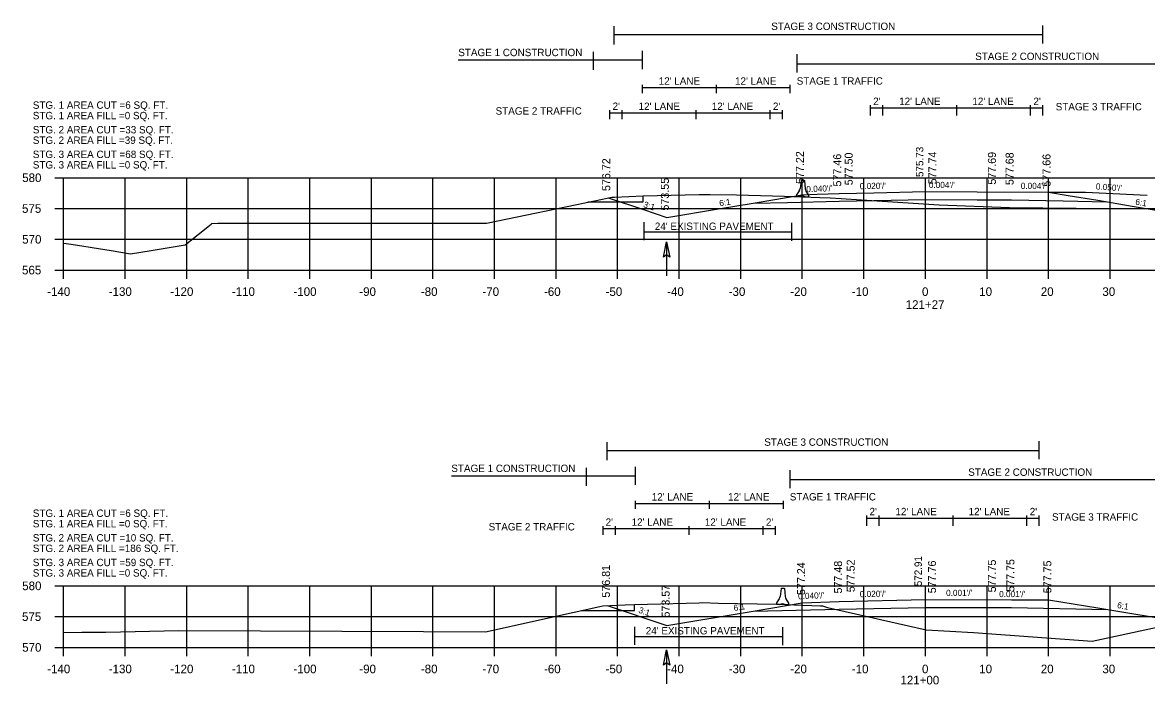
# Model space of a CAD drawing. Extents: x 642114 to 642416, y 286928 to 293347.
# Drawn here: x 642113.6 to 642296.2, y 290961.6 to 291069.2 of the extents above; entities that cross this region are included whole.
import ezdxf

# ---------------------------------------------------------------- set-up
doc = ezdxf.new("R2010")
doc.units = 0
for name, color, linetype in [('59', 7, 'Continuous'), ('Level 43', 7, 'Continuous'), ('Level 58', 7, 'Continuous'), ('R_Axis', 7, 'Continuous'), ('R_Axis Annot', 7, 'Continuous'), ('R_Draft', 7, 'Continuous'), ('R_Drive', 7, 'Continuous'), ('R_Exist Surface', 7, 'Continuous'), ('R_Exist Surface Annot', 7, 'Continuous'), ('R_Fin Surface', 7, 'Continuous'), ('R_Grid', 7, 'Continuous'), ('R_MOT Barrier', 7, 'Continuous'), ('R_Xsect Elev', 7, 'Continuous'), ('R_Xsect Slope', 7, 'Continuous')]:
    doc.layers.add(name, color=color, linetype=linetype)

# ---------------------------------------------------------------- blocks, each defined once
blk = doc.blocks.new('BARRIER WALL X-SECTION')
at = {"layer": 'R_MOT Barrier'}
for p, q in [((0.8, 2.59), (0.63, 1.29)), ((0.8, 2.59), (0.87, 2.65)), ((0.87, 2.65), (1.24, 2.64)), ((1.24, 2.64), (1.31, 2.58)), ((1.31, 2.58), (1.42, 1.27)), ((0.48, 0.9), (0, 0.25)), ((0, 0.25), (0, 0)), ((0.5, -0.01), (0, 0)), ((0.5, -0.01), (1, 0.15)), ((1, 0.15), (1.5, -0.03)), ((1.56, 0.88), (2, 0.21)), ((2, 0.21), (2, -0.04)), ((1.5, -0.03), (2, -0.04))]:
    blk.add_line(p, q, dxfattribs=at)
for centre, start, end in [((-0.2, 1.39), 323.8622, 352.8452), ((2.25, 1.34), 184.8632, 213.8462)]:
    blk.add_arc(centre, 0.833, start, end, dxfattribs=at)
blk = doc.blocks.new('FA')
at = {"layer": 'Level 43'}
blk.add_lwpolyline([(7.94, 0), (0, 0)], dxfattribs=at)
at = {"layer": 'Level 58'}
blk.add_lwpolyline([(4.34, 0.75), (7.94, 0), (4.34, -0.75), (4.94, 0)], close=True, dxfattribs=at)

msp = doc.modelspace()

# ---------------------------------------------------------------- linework, layer by layer
at = {"layer": 'R_Axis'}
for p, q in [((642118.84, 291043.95), (642120.24, 291043.95)), ((642120.24, 291028.95), (642120.24, 291043.95)), ((642118.84, 291038.95), (642120.24, 291038.95)), ((642118.84, 291033.95), (642120.24, 291033.95)), ((642118.84, 291028.95), (642120.24, 291028.95)), ((642120.24, 291028.95), (642400.24, 291028.95)), ((642120.24, 291027.55), (642120.24, 291028.95)), ((642130.24, 291027.55), (642130.24, 291028.95)), ((642140.24, 291027.55), (642140.24, 291028.95)), ((642150.24, 291027.55), (642150.24, 291028.95)), ((642160.24, 291027.55), (642160.24, 291028.95)), ((642170.24, 291027.55), (642170.24, 291028.95)), ((642180.24, 291027.55), (642180.24, 291028.95)), ((642190.24, 291027.55), (642190.24, 291028.95)), ((642200.24, 291027.55), (642200.24, 291028.95)), ((642210.24, 291027.55), (642210.24, 291028.95)), ((642220.24, 291027.55), (642220.24, 291028.95)), ((642230.24, 291027.55), (642230.24, 291028.95)), ((642240.24, 291027.55), (642240.24, 291028.95)), ((642250.24, 291027.55), (642250.24, 291028.95)), ((642260.24, 291027.55), (642260.24, 291028.95)), ((642270.24, 291027.55), (642270.24, 291028.95)), ((642280.24, 291027.55), (642280.24, 291028.95)), ((642290.24, 291027.55), (642290.24, 291028.95)), ((642118.84, 290977.66), (642120.24, 290977.66)), ((642120.24, 290967.66), (642120.24, 290977.66)), ((642118.84, 290972.66), (642120.24, 290972.66)), ((642118.84, 290967.66), (642120.24, 290967.66)), ((642120.24, 290967.66), (642400.24, 290967.66)), ((642120.24, 290966.26), (642120.24, 290967.66)), ((642130.24, 290966.26), (642130.24, 290967.66)), ((642140.24, 290966.26), (642140.24, 290967.66)), ((642150.24, 290966.26), (642150.24, 290967.66)), ((642160.24, 290966.26), (642160.24, 290967.66)), ((642170.24, 290966.26), (642170.24, 290967.66)), ((642180.24, 290966.26), (642180.24, 290967.66)), ((642190.24, 290966.26), (642190.24, 290967.66)), ((642200.24, 290966.26), (642200.24, 290967.66)), ((642210.24, 290966.26), (642210.24, 290967.66)), ((642220.24, 290966.26), (642220.24, 290967.66)), ((642230.24, 290966.26), (642230.24, 290967.66)), ((642240.24, 290966.26), (642240.24, 290967.66)), ((642250.24, 290966.26), (642250.24, 290967.66)), ((642260.24, 290966.26), (642260.24, 290967.66)), ((642270.24, 290966.26), (642270.24, 290967.66)), ((642280.24, 290966.26), (642280.24, 290967.66)), ((642290.24, 290966.26), (642290.24, 290967.66))]:
    msp.add_line(p, q, dxfattribs=at)
at = {"layer": 'R_Drive'}
msp.add_lwpolyline([(642280.24, 291041.62), (642286.24, 291041.6)], dxfattribs=at)
at = {"layer": 'R_Exist Surface'}
for points in [[(642232.25, 291039.84), (642237.84, 291039.95), (642246.24, 291040.12), (642251.83, 291040.23), (642260.24, 291040.4), (642268.63, 291040.37), (642274.24, 291040.35), (642282.63, 291040.18), (642289.73, 291040.04)], [(642232.25, 290973.57), (642246.24, 290973.85), (642260.24, 290974.13), (642274.24, 290974.12), (642289.84, 290973.81)]]:
    msp.add_lwpolyline(points, dxfattribs=at)
at = {"layer": 'R_Exist Surface Annot'}
for points in [[(642120.24, 291033.32), (642121.45, 291033.15), (642127.96, 291032.14), (642131.13, 291031.6), (642134.47, 291032.12), (642139.99, 291033.05), (642144.24, 291036.43), (642144.33, 291036.54), (642145.28, 291036.55), (642188.96, 291036.57), (642206.75, 291040.28), (642209.3, 291040.8), (642209.75, 291040.82), (642214.39, 291041.01), (642223.5, 291041.21), (642225.27, 291041.25), (642229.55, 291041.15), (642237.32, 291040.97), (642243.09, 291040.75), (642244.75, 291040.69), (642246.54, 291040.56), (642249.85, 291040.37), (642262.47, 291039.54), (642273.91, 291039.12), (642284.72, 291038.99), (642291.45, 291038.97), (642301.77, 291038.85)], [(642120.24, 290970.1), (642123.19, 290970.12), (642127.09, 290970.16), (642138.96, 290970.39), (642178.68, 290970.22), (642188.8, 290970.19), (642203.18, 290973.39), (642207.35, 290974.32), (642207.84, 290974.44), (642211.46, 290974.59), (642212.96, 290974.65), (642223.5, 290974.92), (642224, 290974.93), (642226.55, 290974.87), (642236.02, 290974.66), (642243.2, 290974.4), (642243.5, 290974.39), (642244.32, 290974.16), (642260.36, 290970.54), (642268.03, 290970.1), (642287.34, 290968.68), (642291.1, 290969.48), (642297.87, 290970.93)]]:
    msp.add_lwpolyline(points, dxfattribs=at)
at = {"layer": 'R_Fin Surface'}
for points in [[(642208.71, 291040.68), (642214.44, 291038.77), (642218.24, 291037.5), (642226.64, 291038.9), (642232.25, 291039.84), (642235.44, 291040.37), (642240.24, 291041.17), (642242.64, 291041.27), (642246.24, 291041.41), (642251.83, 291041.52), (642260.24, 291041.69), (642268.63, 291041.66), (642280.24, 291041.62)], [(642280.24, 291041.62), (642283.43, 291041.09), (642288.23, 291040.29), (642293.83, 291039.35), (642302.24, 291037.95), (642309.55, 291035.51), (642318.89, 291038.63)], [(642286.24, 291041.6), (642296.24, 291041.1)], [(642208.54, 290974.46), (642218.24, 290971.23), (642232.25, 290973.57), (642240.24, 290974.9), (642246.24, 290975.14), (642260.24, 290975.42), (642274.24, 290975.41), (642280.24, 290975.41)], [(642280.24, 290975.41), (642288.23, 290974.08), (642302.24, 290971.74)]]:
    msp.add_lwpolyline(points, dxfattribs=at)
at = {"layer": 'R_Grid'}
for p, q in [((642120.24, 291043.95), (642400.24, 291043.95)), ((642120.24, 291028.95), (642120.24, 291043.95)), ((642130.24, 291028.95), (642130.24, 291043.95)), ((642140.24, 291028.95), (642140.24, 291043.95)), ((642150.24, 291028.95), (642150.24, 291043.95)), ((642160.24, 291028.95), (642160.24, 291043.95)), ((642170.24, 291028.95), (642170.24, 291043.95)), ((642180.24, 291028.95), (642180.24, 291043.95)), ((642190.24, 291028.95), (642190.24, 291043.95)), ((642200.24, 291028.95), (642200.24, 291043.95)), ((642210.24, 291028.95), (642210.24, 291043.95)), ((642220.24, 291028.95), (642220.24, 291043.95)), ((642230.24, 291028.95), (642230.24, 291043.95)), ((642240.24, 291028.95), (642240.24, 291043.95)), ((642250.24, 291028.95), (642250.24, 291043.95)), ((642260.24, 291028.95), (642260.24, 291043.95)), ((642270.24, 291028.95), (642270.24, 291043.95)), ((642280.24, 291028.95), (642280.24, 291043.95)), ((642290.24, 291028.95), (642290.24, 291043.95)), ((642120.24, 291038.95), (642400.24, 291038.95)), ((642120.24, 291033.95), (642400.24, 291033.95)), ((642120.24, 291028.95), (642400.24, 291028.95)), ((642120.24, 290977.66), (642400.24, 290977.66)), ((642120.24, 290967.66), (642120.24, 290977.66)), ((642130.24, 290967.66), (642130.24, 290977.66)), ((642140.24, 290967.66), (642140.24, 290977.66)), ((642150.24, 290967.66), (642150.24, 290977.66)), ((642160.24, 290967.66), (642160.24, 290977.66)), ((642170.24, 290967.66), (642170.24, 290977.66)), ((642180.24, 290967.66), (642180.24, 290977.66)), ((642190.24, 290967.66), (642190.24, 290977.66)), ((642200.24, 290967.66), (642200.24, 290977.66)), ((642210.24, 290967.66), (642210.24, 290977.66)), ((642220.24, 290967.66), (642220.24, 290977.66)), ((642230.24, 290967.66), (642230.24, 290977.66)), ((642240.24, 290967.66), (642240.24, 290977.66)), ((642250.24, 290967.66), (642250.24, 290977.66)), ((642260.24, 290967.66), (642260.24, 290977.66)), ((642270.24, 290967.66), (642270.24, 290977.66)), ((642280.24, 290967.66), (642280.24, 290977.66)), ((642290.24, 290967.66), (642290.24, 290977.66)), ((642120.24, 290972.66), (642400.24, 290972.66)), ((642120.24, 290967.66), (642400.24, 290967.66))]:
    msp.add_line(p, q, dxfattribs=at)
at = {"layer": 'R_Xsect Elev'}
for p, q in [((642279.33, 291065.76), (642279.33, 291068.69)), ((642209.67, 291065.62), (642209.67, 291068.55)), ((642209.67, 291067.2), (642279.33, 291067.2)), ((642206.33, 291061.47), (642206.33, 291064.4)), ((642214.29, 291061.61), (642214.29, 291064.54)), ((642239.39, 291061.07), (642239.39, 291064)), ((642184.36, 291063.08), (642214.29, 291063.08)), ((642239.39, 291062.45), (642319.24, 291062.45)), ((642214.29, 291057.7), (642214.29, 291059.02)), ((642214.29, 291058.61), (642238.29, 291058.61)), ((642226.29, 291057.7), (642226.29, 291059.02)), ((642238.29, 291057.7), (642238.29, 291059.02)), ((642209, 291053.48), (642209, 291054.91)), ((642209, 291054.5), (642237, 291054.5)), ((642211, 291053.48), (642211, 291054.91)), ((642223, 291053.48), (642223, 291054.91)), ((642235, 291053.48), (642235, 291054.91)), ((642237, 291053.48), (642237, 291054.91)), ((642251.33, 291054.07), (642251.33, 291055.72)), ((642251.33, 291055.31), (642279.33, 291055.31)), ((642253.33, 291054.07), (642253.33, 291055.72)), ((642265.33, 291054.07), (642265.33, 291055.72)), ((642277.33, 291054.07), (642277.33, 291055.72)), ((642279.33, 291054.07), (642279.33, 291055.72)), ((642214.53, 291033.79), (642214.53, 291036.71)), ((642238.53, 291033.7), (642238.53, 291036.62)), ((642214.53, 291035.14), (642238.53, 291035.14)), ((642278.72, 290998.22), (642278.72, 291001.15)), ((642208.54, 290998.08), (642208.54, 291001.01)), ((642208.54, 290999.66), (642278.72, 290999.66)), ((642205.2, 290993.92), (642205.2, 290996.85)), ((642213.16, 290994.06), (642213.16, 290996.99)), ((642238.26, 290993.53), (642238.26, 290996.46)), ((642183.23, 290995.53), (642213.16, 290995.53)), ((642238.26, 290994.91), (642314.9, 290994.91)), ((642213.16, 290990.16), (642213.16, 290991.48)), ((642213.16, 290991.06), (642237.16, 290991.06)), ((642225.16, 290990.16), (642225.16, 290991.48)), ((642237.16, 290990.16), (642237.16, 290991.48)), ((642250.72, 290987.43), (642250.72, 290989.09)), ((642250.72, 290988.67), (642278.72, 290988.67)), ((642252.72, 290987.43), (642252.72, 290989.09)), ((642264.72, 290987.43), (642264.72, 290989.09)), ((642276.72, 290987.43), (642276.72, 290989.09)), ((642278.72, 290987.43), (642278.72, 290989.09)), ((642207.87, 290985.94), (642207.87, 290987.37)), ((642207.87, 290986.96), (642235.87, 290986.96)), ((642209.87, 290985.94), (642209.87, 290987.37)), ((642221.87, 290985.94), (642221.87, 290987.37)), ((642233.87, 290985.94), (642233.87, 290987.37)), ((642235.87, 290985.94), (642235.87, 290987.37)), ((642213.06, 290968.09), (642213.06, 290971.02)), ((642237.06, 290968), (642237.06, 290970.93)), ((642213.06, 290969.44), (642237.06, 290969.44))]:
    msp.add_line(p, q, dxfattribs=at)
for points in [[(642205.39, 291040.01), (642214.39, 291040.01), (642214.39, 291041.01)], [(642204.35, 290973.65), (642212.96, 290973.65), (642212.96, 290974.65)]]:
    msp.add_lwpolyline(points, dxfattribs=at)

# ---------------------------------------------------------------- block references
for p in [(642239.27, 291040.9), (642236.02, 290974.66)]:
    msp.add_blockref('BARRIER WALL X-SECTION', p, dxfattribs=at)
at = {"layer": 'R_Xsect Elev', "xscale": 0.7, "yscale": 0.7, "rotation": 89.99999999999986}
for p in [(642218.2, 291027.99), (642218.2, 290961.72)]:
    msp.add_blockref('FA', p, dxfattribs=at)

# ---------------------------------------------------------------- texts
at = {"layer": '59'}
for s, p in [(' 576.72', (642209.04, 291041.31)), (' 577.22', (642240.5, 291042.46)), (' 577.46', (642246.56, 291042.04)), (' 577.50', (642248.42, 291042.24)), (' 577.74', (642262.03, 291042.4)), (' 577.69', (642271.69, 291042.35)), (' 577.68', (642274.56, 291042.27)), (' 577.66', (642280.56, 291042.03)), (' 573.55', (642218.56, 291038.13)), (' 576.81', (642208.99, 290975.26)), (' 577.24', (642240.69, 290975.69)), (' 577.48', (642246.69, 290975.93)), (' 577.52', (642248.75, 290976.14)), (' 577.76', (642261.95, 290975.97)), (' 577.75', (642271.69, 290976.12)), (' 577.75', (642274.69, 290976.21)), (' 577.75', (642280.69, 290975.97)), (' 573.57', (642218.69, 290972.03))]:
    msp.add_text(s, height=1.3, rotation=90, dxfattribs=at).set_placement(p)
at = {"layer": 'R_Axis Annot'}
for s, p in [('580', (642113.52, 291043.25)), ('575', (642113.49, 291038.25)), ('570', (642113.52, 291033.25)), ('565', (642113.49, 291028.25)), ('-140', (642117.58, 291024.75)), ('-130', (642127.58, 291024.75)), ('-120', (642137.58, 291024.75)), ('-110', (642147.58, 291024.75)), ('-100', (642157.58, 291024.75)), ('-90', (642168.28, 291024.75)), ('-80', (642178.28, 291024.75)), ('-70', (642188.28, 291024.75)), ('-60', (642198.28, 291024.75)), ('-50', (642208.28, 291024.75)), ('-40', (642218.28, 291024.75)), ('-30', (642228.28, 291024.75)), ('-20', (642238.28, 291024.75)), ('-10', (642248.28, 291024.75)), ('0', (642259.68, 291024.75)), ('10', (642268.98, 291024.75)), ('20', (642278.98, 291024.75)), ('30', (642288.98, 291024.75)), ('121+27', (642257.03, 291022.65)), ('580', (642113.52, 290976.96)), ('575', (642113.49, 290971.96)), ('570', (642113.52, 290966.96)), ('-140', (642117.58, 290963.46)), ('-130', (642127.58, 290963.46)), ('-120', (642137.58, 290963.46)), ('-110', (642147.58, 290963.46)), ('-100', (642157.58, 290963.46)), ('-90', (642168.28, 290963.46)), ('-80', (642178.28, 290963.46)), ('-70', (642188.28, 290963.46)), ('-60', (642198.28, 290963.46)), ('-50', (642208.28, 290963.46)), ('-40', (642218.28, 290963.46)), ('-30', (642228.28, 290963.46)), ('-20', (642238.28, 290963.46)), ('-10', (642248.28, 290963.46)), ('0', (642259.68, 290963.46)), ('10', (642268.98, 290963.46)), ('20', (642278.98, 290963.46)), ('30', (642288.98, 290963.46)), ('121+00', (642256.18, 290961.65))]:
    msp.add_text(s, height=1.4, dxfattribs=at).set_placement(p)
at = {"layer": 'R_Draft'}
for s, p in [('STG. 1 AREA CUT =6 SQ. FT.', (642115.24, 291055.15)), ('STG. 1 AREA FILL =0 SQ. FT.', (642115.24, 291053.45)), ('STG. 2 AREA CUT =33 SQ. FT.', (642115.24, 291051.15)), ('STG. 2 AREA FILL =39 SQ. FT.', (642115.24, 291049.45)), ('STG. 3 AREA CUT =68 SQ. FT.', (642115.24, 291047.15)), ('STG. 3 AREA FILL =0 SQ. FT.', (642115.24, 291045.45)), ('STG. 1 AREA CUT =6 SQ. FT.', (642115.24, 290988.86)), ('STG. 1 AREA FILL =0 SQ. FT.', (642115.24, 290987.16)), ('STG. 2 AREA CUT =10 SQ. FT.', (642115.24, 290984.86)), ('STG. 2 AREA FILL =186 SQ. FT.', (642115.24, 290983.16)), ('STG. 3 AREA CUT =59 SQ. FT.', (642115.24, 290980.86)), ('STG. 3 AREA FILL =0 SQ. FT.', (642115.24, 290979.16))]:
    msp.add_text(s, height=1.2, dxfattribs=at).set_placement(p)
at = {"layer": 'R_Xsect Elev'}
for s, p in [('STAGE 3 CONSTRUCTION', (642235.19, 291067.95)), ('STAGE 1 CONSTRUCTION', (642184.36, 291063.7)), ('STAGE 2 CONSTRUCTION', (642268.32, 291063.07)), ("12' LANE", (642216.91, 291059.07)), ("12' LANE", (642229.31, 291059.06)), ('STAGE 1 TRAFFIC', (642239.33, 291059.07)), ("2'", (642209.42, 291054.96)), ("12' LANE", (642213.64, 291054.96)), ("12' LANE", (642225.53, 291054.96)), ("2'", (642235.46, 291054.96)), ("2'", (642251.75, 291055.77)), ("12' LANE", (642255.97, 291055.77)), ("12' LANE", (642267.86, 291055.77)), ("2'", (642277.78, 291055.77)), ('STAGE 3 TRAFFIC', (642281.4, 291054.89)), ('STAGE 2 TRAFFIC', (642190.42, 291054.2)), ("24' EXISTING PAVEMENT", (642216.28, 291035.47)), ('STAGE 3 CONSTRUCTION', (642234.06, 291000.41)), ('STAGE 1 CONSTRUCTION', (642183.23, 290996.15)), ('STAGE 2 CONSTRUCTION', (642267.19, 290995.53)), ("12' LANE", (642215.78, 290991.52)), ("12' LANE", (642228.18, 290991.52)), ('STAGE 1 TRAFFIC', (642238.2, 290991.53)), ("2'", (642251.15, 290989.13)), ("12' LANE", (642255.37, 290989.13)), ("12' LANE", (642267.25, 290989.13)), ("2'", (642277.18, 290989.13)), ("2'", (642208.29, 290987.41)), ("12' LANE", (642212.51, 290987.41)), ("12' LANE", (642224.4, 290987.41)), ("2'", (642234.33, 290987.41)), ('STAGE 3 TRAFFIC', (642280.8, 290988.25)), ('STAGE 2 TRAFFIC', (642189.29, 290986.66)), ("24' EXISTING PAVEMENT", (642214.81, 290969.77))]:
    msp.add_text(s, height=1.2, dxfattribs=at).set_placement(p)
for s, p in [('575.73', (642259.9, 291044.07)), ('572.91', (642259.66, 290977.59))]:
    msp.add_text(s, height=1.2, rotation=90, dxfattribs=at).set_placement(p)
at = {"layer": 'R_Xsect Slope'}
for s, rotation, p in [("0.020'/'", 1.1458, (642249.58, 291042.08)), ("0.004'/'", 359.8064, (642260.79, 291042.29)), ("0.004'/'", 359.8064, (642275.72, 291042.13)), ("0.050'/'", 355.8203, (642287.89, 291042.06)), ("0.040'/'", 2.2906, (642240.91, 291041.59)), ('3:1', 341.5668, (642214.34, 291039.2)), ('6:1', 9.4642, (642226.83, 291039.29)), ('6:1', 350.5358, (642294.28, 291039.58)), ("0.040'/'", 2.2906, (642239.57, 290975.47)), ("0.020'/'", 1.1458, (642249.58, 290975.81)), ("0.001'/'", 359.9656, (642263.59, 290976.02)), ("0.001'/'", 359.9656, (642272.21, 290975.83)), ('3:1', 341.5668, (642213.55, 290973.32)), ('6:1', 9.4642, (642229.16, 290973.56)), ('6:1', 350.5358, (642291.32, 290974.07))]:
    msp.add_text(s, height=1, rotation=rotation, dxfattribs=at).set_placement(p)

doc.saveas('drawing.dxf')
